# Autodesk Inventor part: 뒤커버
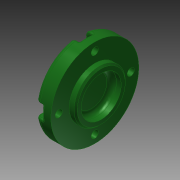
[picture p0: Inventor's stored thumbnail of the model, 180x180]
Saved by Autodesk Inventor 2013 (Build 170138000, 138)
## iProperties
Created: 2015-11
Part Number: 뒤커버
Material: 알루미늄 6061
Document SubType Name: Modeling
Designer: mduedu
Density: 1 g/cm^3
Author: mduedu
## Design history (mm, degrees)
sketch "스케치1"
  geometry: L1 (-7, 0)-(7, 0); L2 (-7, 0)-(-7, 27.5); L3 (-7, 27.5)-(3, 27.5); L4 (3, 27.5)-(3, 16); L5 (3, 16)-(7, 16); L6 (7, 16)-(7, 0); 2 further points
  constraints: 12 end point, 3 perpendicular, 2 parallel, 1 coincident, 1 horizontal, 1 midpoint
  dimensions: "d0" = 14 distance of L1.start L1.end; "d1" = 55 diameter of L3 L1; "d2" = 4 distance of L4.end L5.end; "d3" = 32 diameter of L5 L1
revolve "회전1" sketch "스케치1" stored, may be unused: angle "d4" = 90 deg
hole "구멍1" diameter "d7" = 25; stored, may be unused: countersink angle "d11" = 90 deg, drill point angle "d13" = 0 deg; dims "d8" = 6, "d9" = 4, "d10" = 2, "d12" = 6, "d61" = 10, "d62" = 10
fillet "모깎기2" dims "d36" = 3
fillet "모깎기3" dims "d37" = 3
sketch "스케치2" dims "d39" = 45
  geometry: C1 r 12.846 at (0, 0) reference; C2 r 24.5 at (0, 0) reference; 6 further points
  constraints: 2 vertical alignment, 1 coincident, 7 other
  dimensions: "d42" = 360 deg dimension on point (0, 0) point (0, 22.5) (derived)
sketch "스케치3"
  geometry: 8 further points
  constraints: 4 coincident
hole "구멍4" sketch "스케치3" at (-22.5, 0), (0, -22.5), (22.5, 0), (0, 22.5) diameter "d44" = 4.5; stored, may be unused: countersink angle "d48" = 90 deg, drill point angle "d50" = 0 deg; dims "d45" = 6, "d46" = 8, "d47" = 4.6, "d49" = 8
sketch "스케치4"
  geometry: L1 (-4, 0)-(-4, -4.708); L2 (4, 0)-(4, -4.708); A1 r 4 centre (0, 0) between (-4, 0) and (4, 0) reference; A2 r 27.5 centre (0, 22.5) between (-4, -4.708) and (4, -4.708) reference; 3 further points
  constraints: 4 end point, 4 point on circle, 2 tangent, 1 parallel, 1 vertical
extrude "돌출1" cut sketch "스케치4" stored distance "d51" = 0; taper "d52" = 0 deg
fillet "모깎기5" dims "d56" = 0.3
fillet "모깎기6" dims "d57" = 1
chamfer "모따기2" distance "d63" = 1; stored, may be unused: second distance "d64" = 2, angle "d65" = 45 deg
node "솔리드1"
pattern_circular "원형 패턴1" dims angle "d54" = 360 deg
